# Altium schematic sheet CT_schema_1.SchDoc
size 469 x 423 mm
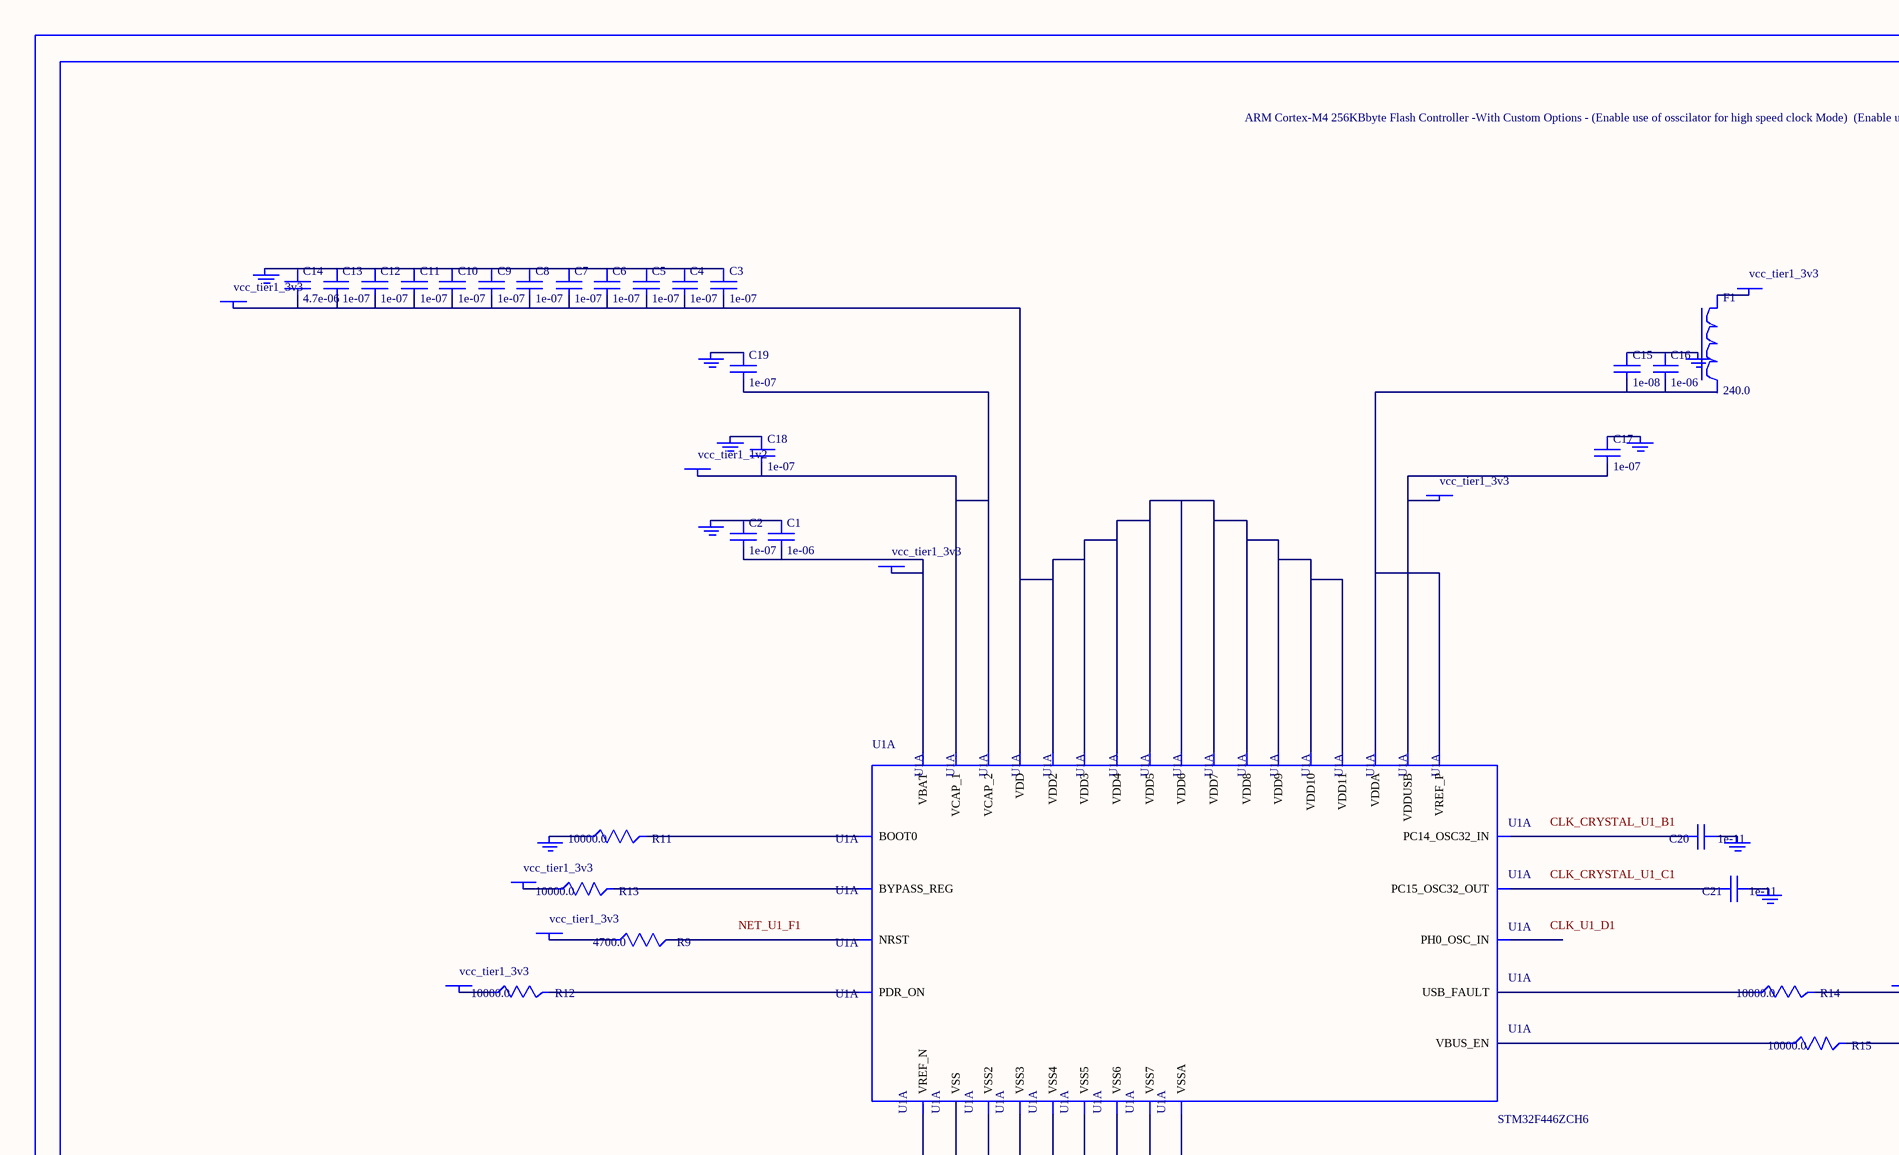
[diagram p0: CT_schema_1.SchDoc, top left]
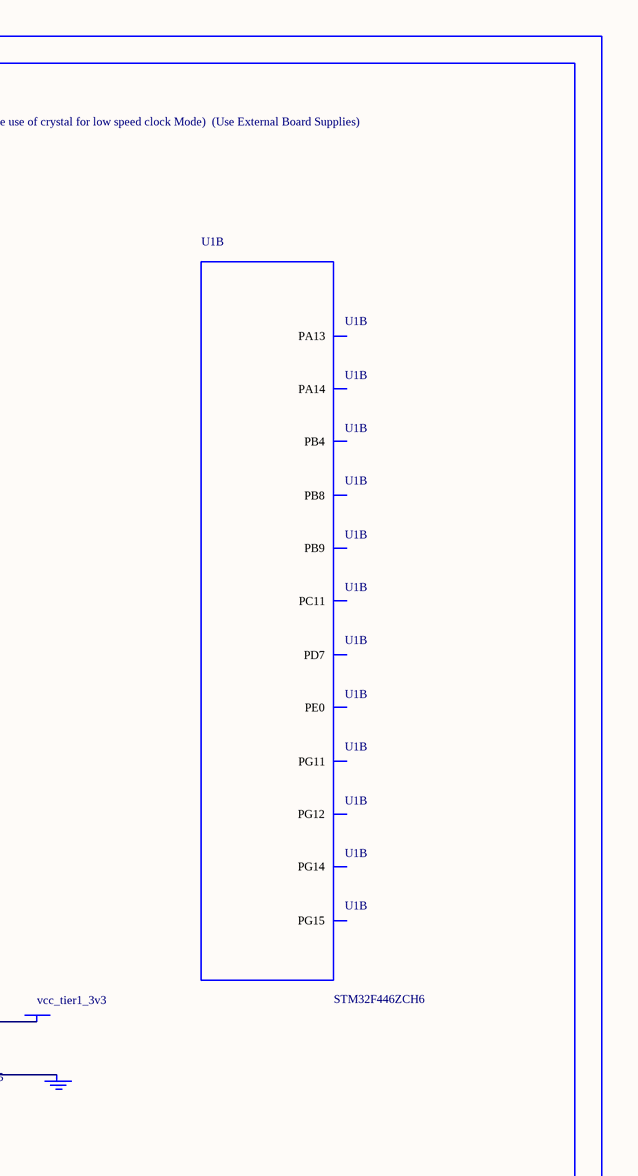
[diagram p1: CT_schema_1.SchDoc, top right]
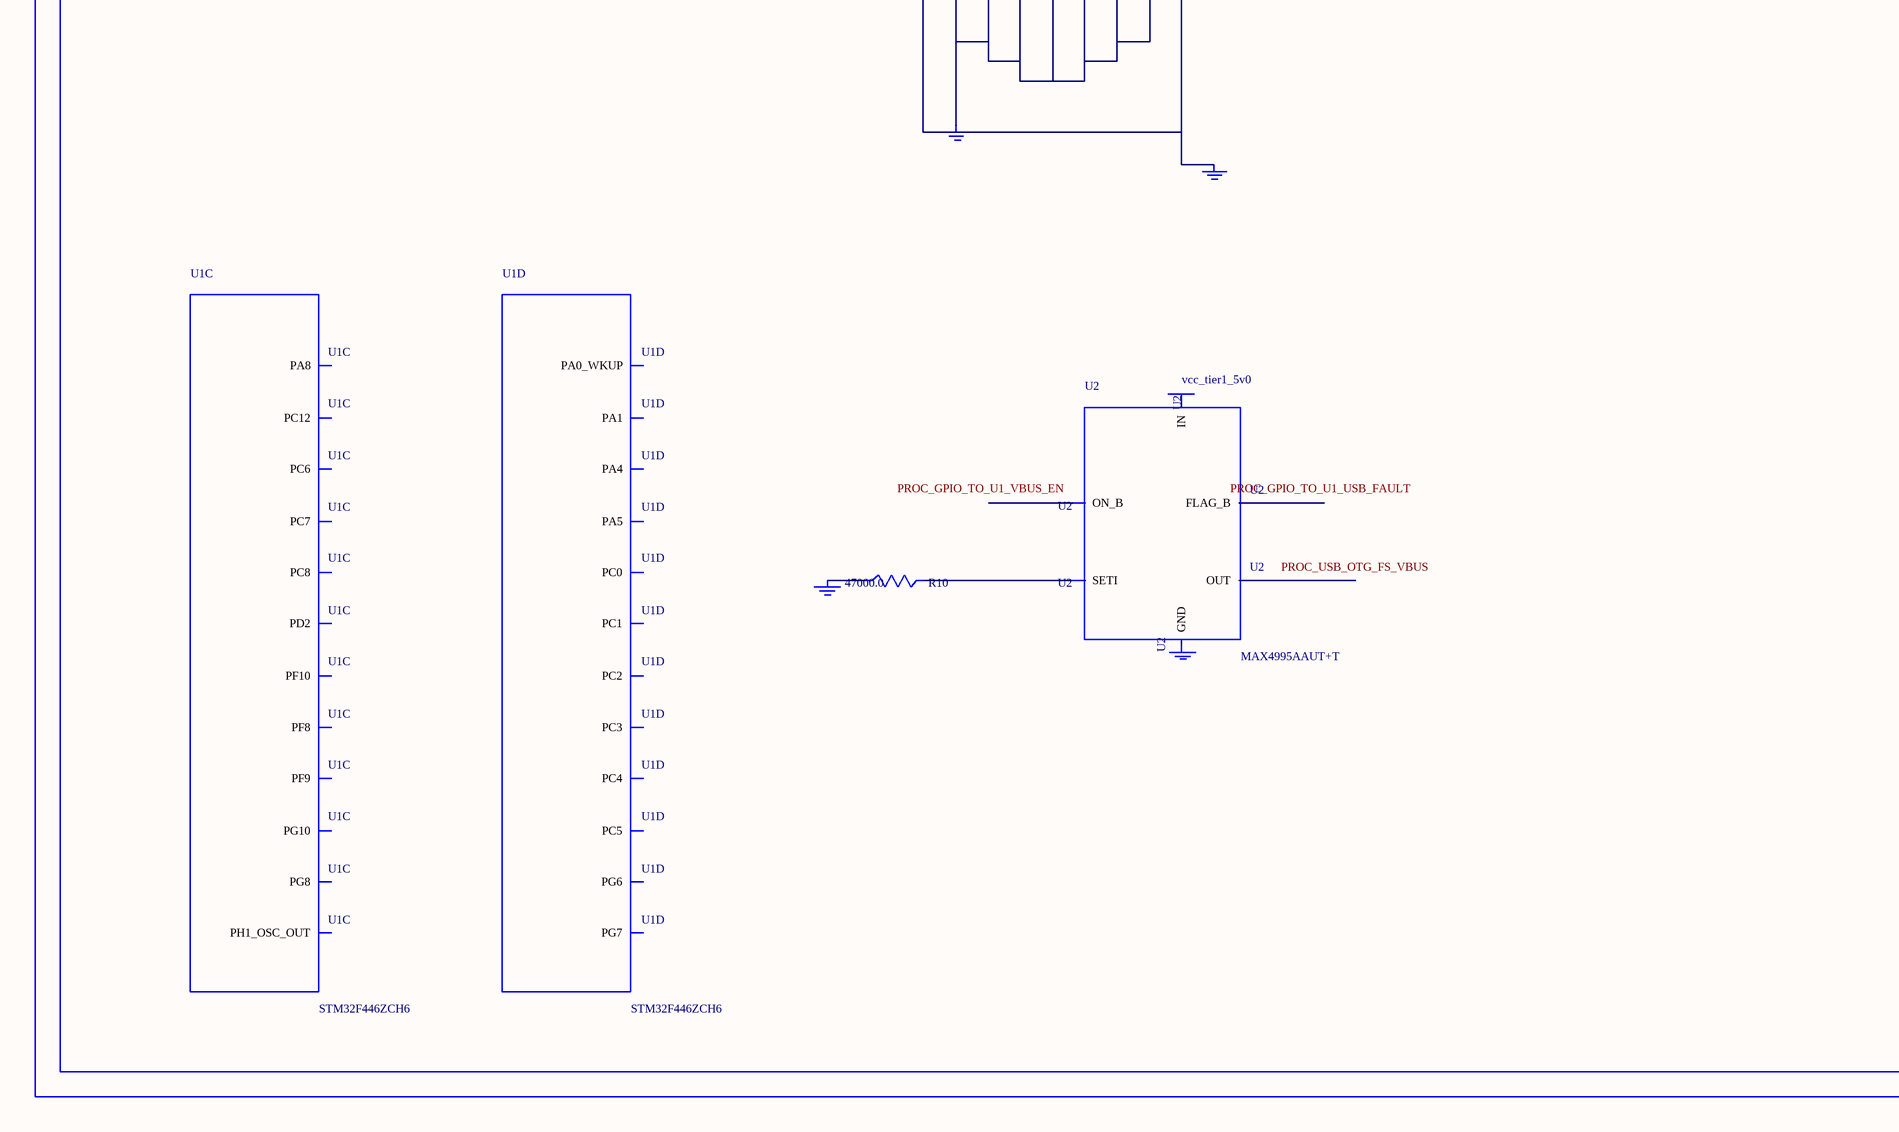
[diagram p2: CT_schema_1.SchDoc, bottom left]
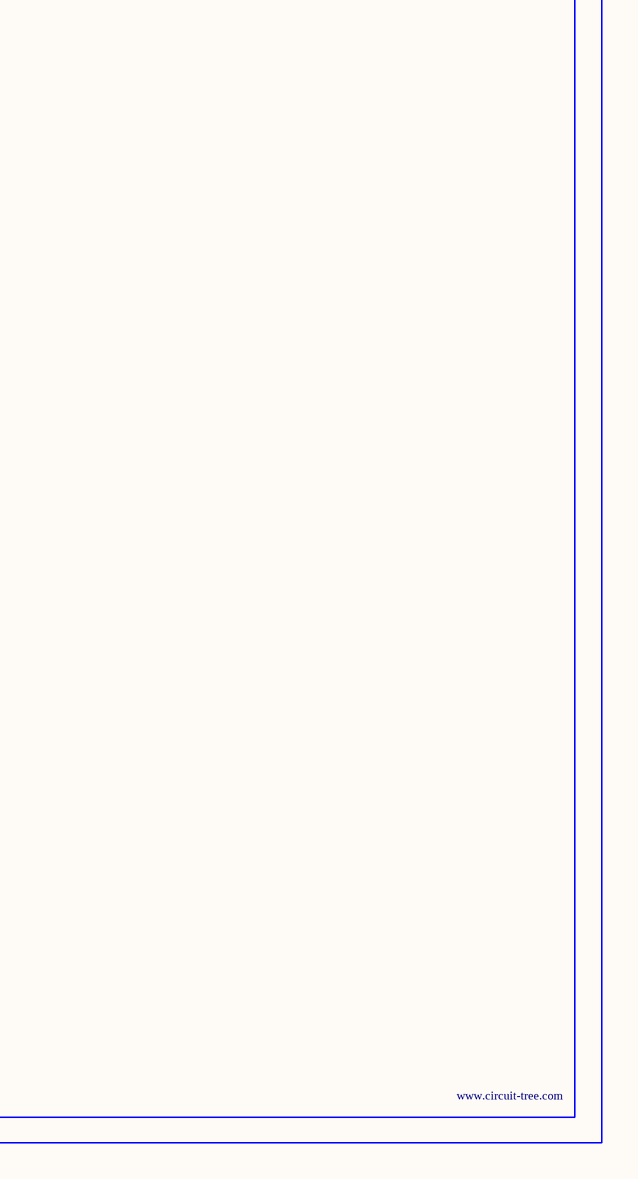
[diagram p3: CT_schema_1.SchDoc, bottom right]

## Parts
BORDER0  (no value)
C1  1e-06  [C0603]
C2  1e-07  [C0603]
C3  1e-07  [C0603]
C4  1e-07  [C0603]
C5  1e-07  [C0603]
C6  1e-07  [C0603]
C7  1e-07  [C0603]
C8  1e-07  [C0603]
C9  1e-07  [C0603]
C10  1e-07  [C0603]
C11  1e-07  [C0603]
C12  1e-07  [C0603]
C13  1e-07  [C0603]
C14  4.7e-06  [C0603]
C15  1e-08  [C0603]
C16  1e-06  [C0603]
C17  1e-07  [C0603]
C18  1e-07  [C0603]
C19  1e-07  [C0603]
C20  1e-11  [C0402]
C21  1e-11  [C0402]
F1  240.0  [L0603]
GND_INSTANCE_0_0  (no value)
GND_INSTANCE_0_1  (no value)
GND_INSTANCE_0_2  (no value)
GND_INSTANCE_0_3  (no value)
GND_INSTANCE_0_4  (no value)
GND_INSTANCE_0_5  (no value)
GND_INSTANCE_0_6  (no value)
GND_INSTANCE_0_7  (no value)
GND_INSTANCE_0_8  (no value)
GND_INSTANCE_0_9  (no value)
GND_INSTANCE_0_10  (no value)
GND_INSTANCE_0_11  (no value)
GND_INSTANCE_0_12  (no value)
GND_INSTANCE_0_13  (no value)
POWER_INSTANCE_0_0  vcc_tier1_3v3
POWER_INSTANCE_0_1  vcc_tier1_3v3
POWER_INSTANCE_0_2  vcc_tier1_3v3
POWER_INSTANCE_0_3  vcc_tier1_3v3
POWER_INSTANCE_0_4  vcc_tier1_3v3
POWER_INSTANCE_0_5  vcc_tier1_3v3
POWER_INSTANCE_0_6  vcc_tier1_1v2
POWER_INSTANCE_0_7  vcc_tier1_3v3
POWER_INSTANCE_0_8  vcc_tier1_3v3
POWER_INSTANCE_0_9  vcc_tier1_5v0
R9  4700.0  [R0603]
R10  47000.0  [R0603]
R11  10000.0  [R0603]
R12  10000.0  [R0603]
R13  10000.0  [R0603]
R14  10000.0  [R0603]
R15  10000.0  [R0603]
U1  STM32F446ZCH6  [UFBGA144]  (parts A,B,C,D of 11)
U2  MAX4995AAUT+T  [SOT-23-6]

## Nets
NetC1_1: C1.1 C2.1 GND_INSTANCE_0_0.0(GND)
NetC1_2: C1.2 C2.2 POWER_INSTANCE_0_0.0(PWR) U1.C2(VBAT)
NetC3_1: C3.1 C4.1 C5.1 C6.1 C7.1 C8.1 C9.1 C10.1 C11.1 C12.1 C13.1 C14.1 GND_INSTANCE_0_2.0(GND)
NetC3_2: C3.2 C4.2 C5.2 C6.2 C7.2 C8.2 C9.2 C10.2 C11.2 C12.2 C13.2 C14.2 POWER_INSTANCE_0_2.0(PWR) U1.D3(VDD) U1.F4(VDD3) U1.F5(VDD4) U1.F6(VDD5) U1.F7(VDD6) U1.F8(VDD7) U1.F9(VDD8) U1.F10(VDD2) U1.G5(VDD9) U1.G6(VDD10) U1.G7(VDD11)
NetC15_1: C15.1 C16.1 GND_INSTANCE_0_1.0(GND)
NetC15_2: C15.2 C16.2 U1.L1(VREF_P) U1.M1(VDDA)
NetC17_1: C17.1 GND_INSTANCE_0_4.0(GND)
NetC17_2: C17.2 POWER_INSTANCE_0_4.0(PWR) U1.C11(VDDUSB)
NetC18_1: C18.1 GND_INSTANCE_0_5.0(GND)
NetC18_2: C18.2 C19.2 POWER_INSTANCE_0_6.0(PWR) U1.G9(VCAP_2) U1.H7(VCAP_1)
NetC19_1: C19.1 GND_INSTANCE_0_6.0(GND)
NetC20_1: C20.1 GND_INSTANCE_0_7.0(GND)
NetC20_2: C20.2 U1.B1(PC14_OSC32_IN)
NetC21_1: C21.1 GND_INSTANCE_0_8.0(GND)
NetC21_2: C21.2 U1.C1(PC15_OSC32_OUT)
NetF1_1: F1.1 POWER_INSTANCE_0_1.0(PWR)
NetGND_INSTANCE_0_3_0: GND_INSTANCE_0_3.0(GND) R11.1
NetGND_INSTANCE_0_9_0: GND_INSTANCE_0_9.0(GND) R15.2
NetGND_INSTANCE_0_10_0: GND_INSTANCE_0_10.0(GND) U1.J1(VSSA) U1.K1(VREF_N)
NetGND_INSTANCE_0_11_0: GND_INSTANCE_0_11.0(GND) U1.D2(VSS) U1.E6(VSS2) U1.E7(VSS3) U1.G4(VSS5) U1.G8(VSS6) U1.G10(VSS4) U1.H6(VSS7)
NetGND_INSTANCE_0_12_0: GND_INSTANCE_0_12.0(GND) R10.1
NetPOWER_INSTANCE_0_3_0: POWER_INSTANCE_0_3.0(PWR) R12.1
NetPOWER_INSTANCE_0_5_0: POWER_INSTANCE_0_5.0(PWR) R13.1
NetPOWER_INSTANCE_0_7_0: POWER_INSTANCE_0_7.0(PWR) R14.2
NetPOWER_INSTANCE_0_8_0: POWER_INSTANCE_0_8.0(PWR) R9.1
NetR9_2: R9.2 U1.F1(NRST)
NetR10_2: R10.2 U2.3(SETI)
NetR11_2: R11.2 U1.D5(BOOT0)
NetR12_2: R12.2 U1.E5(PDR_ON)
NetR13_2: R13.2 U1.H5(BYPASS_REG)
NetR14_1: R14.1 U1.A4(USB_FAULT)
NetR15_1: R15.1 U1.A1(VBUS_EN)

Not connected (* = marked no-connect by the designer): F1 2; GND_INSTANCE_0_13 0(GND); POWER_INSTANCE_0_9 0(PWR); U1 A5(PE0) A6(PB4) A9(PD7) A11(PA14) A12(PA13) B5(PB9) B7(PG15) B8(PG12) B10(PC11) C5(PB8) C7(PG14) C8(PG11) C10(PC12) D1(PH0_OSC_IN) D8(PG10) E1(PH1_OSC_OUT) E9(PD2) E12(PA8) F11(PC8) F12(PC7) G1(PF10) G2(PF9) G3(PF8) G11(PG8) G12(PC6) H1(PC0) H2(PC1) H3(PC2) H4(PC3) H10(PG7) H11(PG6) J2(PA0_WKUP) J3(PA4) J4(PC4) K2(PA1) K3(PA5) K4(PC5); U2 1(OUT) 2(GND) 4(ON_B) 5(IN) 6(FLAG_B)

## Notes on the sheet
- Labels drawn without touching a wire or pin: CLK_CRYSTAL_U1_B1, CLK_CRYSTAL_U1_C1, CLK_U1_D1, NET_U1_F1, PROC_GPIO_TO_U1_USB_FAULT, PROC_GPIO_TO_U1_VBUS_EN, PROC_USB_OTG_FS_VBUS

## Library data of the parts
BORDER0 = BORDER_PAGE0
C1 C16 = C0603C105K3RACTU
C2-C13 C17-C19 = 06035C104K4Z2A
C14 = GRM188R6YA475KE15D
C15 = 06035C103K4Z2A
C20 C21 = C0402C100K3GACTU
F1 = Z0603C241ASMST
GND_INSTANCE_0_0-GND_INSTANCE_0_13 = GND
POWER_INSTANCE_0_0-POWER_INSTANCE_0_9 = PWR
R9 = RC0603JR-074K7L
R10 = RC0603JR-0747KL
R11-R15 = RC0603JR-0710KL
